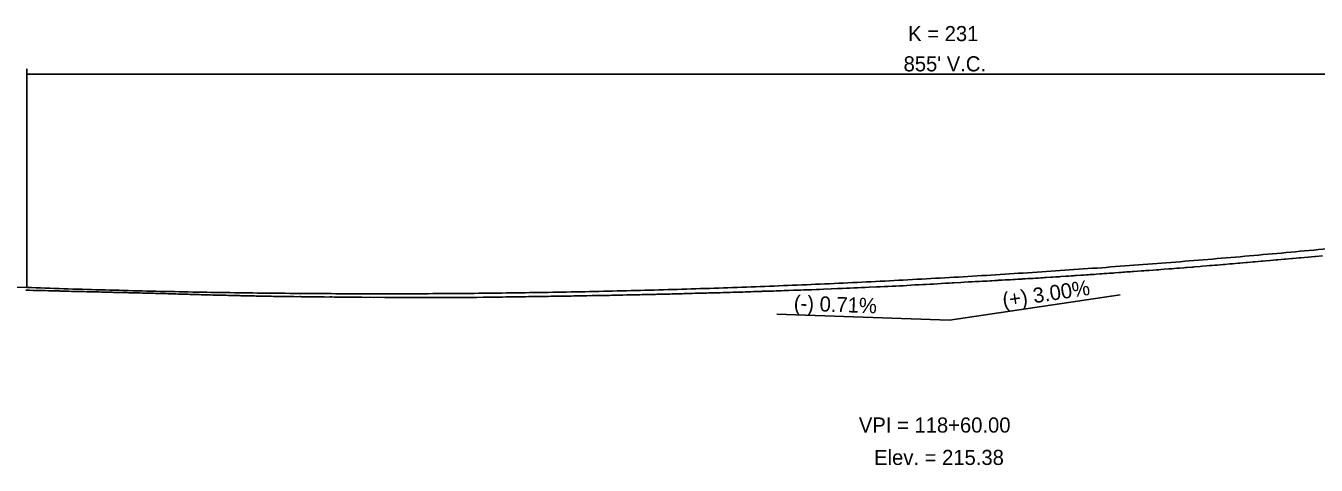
# Model space of a CAD drawing. Extents: x 1838386 to 1955906, y 719739 to 834437.
# Drawn here: x 1888795 to 1889393, y 826143 to 826346 of the extents above; entities that cross this region are included whole.
import ezdxf

# ---------------------------------------------------------------- set-up
doc = ezdxf.new("R2010")
doc.units = 0
for name, color, linetype in [('RD_DDB_GradeTX', 7, 'Continuous'), ('RD_DDB_Profile_EX', 7, 'Continuous'), ('RD_DDB_Profile_Lbl', 7, 'Continuous'), ('RD_DDB_Profile_PR', 7, 'Continuous'), ('RD_DDB_VCLbl', 7, 'Continuous')]:
    doc.layers.add(name, color=color, linetype=linetype)

msp = doc.modelspace()

# ---------------------------------------------------------------- linework, layer by layer
at = {"layer": 'RD_DDB_GradeTX'}
for p in [(1889302.2, 826221.86), (1889143.13, 826212.86)]:
    msp.add_line(p, (1889223.08, 826210.01), dxfattribs=at)
at = {"layer": 'RD_DDB_Profile_EX'}
for points in [[(1889291.05, 826231.37), (1889292.84, 826231.51), (1889293.65, 826231.56), (1889294.55, 826231.63), (1889295.3, 826231.67), (1889295.97, 826231.73), (1889297.05, 826231.8), (1889298.06, 826231.88), (1889298.87, 826231.92), (1889299.72, 826232), (1889301.56, 826232.13), (1889302.49, 826232.18), (1889303.48, 826232.28), (1889304.27, 826232.33), (1889305.08, 826232.39), (1889306.91, 826232.52), (1889307.75, 826232.58), (1889308.59, 826232.64), (1889310.37, 826232.76), (1889312.09, 826232.88), (1889313.08, 826232.93), (1889314.13, 826233.03), (1889314.85, 826233.07), (1889315.59, 826233.13), (1889317.55, 826233.27), (1889319.1, 826233.38), (1889320.07, 826233.43), (1889321.01, 826233.53), (1889322.61, 826233.64), (1889324.77, 826233.81), (1889325.44, 826233.86), (1889326.14, 826233.92), (1889327.28, 826233.98), (1889328.5, 826234.11), (1889329.63, 826234.19), (1889331.67, 826234.35), (1889332.43, 826234.4), (1889333.13, 826234.47), (1889335.45, 826234.65), (1889336.04, 826234.7), (1889336.64, 826234.75), (1889339.21, 826234.97), (1889340.15, 826235.05), (1889342.35, 826235.23), (1889343.65, 826235.33), (1889344.85, 826235.39), (1889346.12, 826235.54), (1889346.64, 826235.58), (1889347.16, 826235.62), (1889349.89, 826235.86), (1889350.66, 826235.93), (1889353.04, 826236.13), (1889354.17, 826236.22), (1889356.81, 826236.46), (1889357.24, 826236.49), (1889357.67, 826236.53), (1889359.08, 826236.61), (1889360.59, 826236.78), (1889361.19, 826236.83), (1889363.74, 826237.05), (1889364.7, 826237.13), (1889367.52, 826237.37), (1889367.86, 826237.4), (1889368.21, 826237.43), (1889369.63, 826237.51), (1889371.71, 826237.74), (1889374.45, 826237.97), (1889375.21, 826238.04), (1889378.24, 826238.32), (1889378.72, 826238.36), (1889381.7, 826238.62), (1889382.23, 826238.67), (1889383.78, 826238.76), (1889385.19, 826238.93), (1889385.74, 826238.98), (1889389.24, 826239.3), (1889392.45, 826239.59), (1889392.76, 826239.61), (1889395.94, 826239.91)], [(1889159.22, 826224.2), (1889161.29, 826224.31), (1889162.83, 826224.33), (1889164.8, 826224.44), (1889168.24, 826224.58), (1889171.22, 826224.71), (1889171.81, 826224.73), (1889173.33, 826224.76), (1889175.33, 826224.87), (1889176.93, 826224.9), (1889178.82, 826225.03), (1889180.53, 826225.06), (1889182.33, 826225.19), (1889184.05, 826225.23), (1889185.85, 826225.36), (1889189.36, 826225.52), (1889191.04, 826225.55), (1889192.86, 826225.67), (1889194.65, 826225.72), (1889196.54, 826225.84), (1889198.18, 826225.88), (1889199.93, 826226), (1889201.63, 826226.05), (1889203.37, 826226.17), (1889205.17, 826226.23), (1889207.05, 826226.37), (1889208.77, 826226.43), (1889210.77, 826226.56), (1889212.31, 826226.62), (1889214.17, 826226.75), (1889215.77, 826226.81), (1889217.59, 826226.95), (1889219.3, 826227.01), (1889221.31, 826227.16), (1889222.92, 826227.22), (1889224.42, 826227.33), (1889224.72, 826227.34), (1889225.04, 826227.37), (1889228.44, 826227.56), (1889229.91, 826227.61), (1889231.87, 826227.76), (1889233.45, 826227.81), (1889234.94, 826227.92), (1889235.26, 826227.93), (1889235.59, 826227.95), (1889237.06, 826228.01), (1889238.45, 826228.11), (1889238.86, 826228.13), (1889239.31, 826228.16), (1889240.61, 826228.21), (1889241.96, 826228.31), (1889242.34, 826228.32), (1889242.71, 826228.35), (1889244.07, 826228.4), (1889245.45, 826228.51), (1889245.8, 826228.53), (1889246.13, 826228.55), (1889247.59, 826228.6), (1889248.96, 826228.71), (1889249.4, 826228.73), (1889249.86, 826228.76), (1889251.21, 826228.81), (1889252.47, 826228.91), (1889253.59, 826228.97), (1889254.77, 826229.02), (1889255.97, 826229.11), (1889256.49, 826229.13), (1889256.99, 826229.17), (1889258.23, 826229.22), (1889259.48, 826229.32), (1889260.43, 826229.37), (1889261.75, 826229.43), (1889262.99, 826229.53), (1889263.56, 826229.55), (1889264.16, 826229.6), (1889265.37, 826229.65), (1889266.51, 826229.74), (1889267.18, 826229.77), (1889267.89, 826229.83), (1889270.01, 826229.95), (1889270.54, 826229.97), (1889271, 826230.01), (1889272.3, 826230.08), (1889273.52, 826230.18), (1889274.11, 826230.2), (1889274.73, 826230.26), (1889277.02, 826230.41), (1889277.72, 826230.44), (1889278.48, 826230.51), (1889279.49, 826230.57), (1889280.53, 826230.65), (1889281.22, 826230.69), (1889281.9, 826230.75), (1889284.03, 826230.88), (1889285.35, 826230.97), (1889286.48, 826231.03), (1889287.54, 826231.12), (1889288.29, 826231.16), (1889289.09, 826231.23), (1889290.11, 826231.29), (1889291.05, 826231.37)], [(1888795.09, 826223.99), (1888796.84, 826223.96), (1888798.5, 826223.89), (1888800.47, 826223.86), (1888802.07, 826223.79), (1888804.12, 826223.76), (1888805.65, 826223.7), (1888807.11, 826223.69), (1888807.43, 826223.67), (1888807.76, 826223.67), (1888809.22, 826223.6), (1888810.61, 826223.6), (1888811, 826223.58), (1888811.4, 826223.58), (1888812.79, 826223.52), (1888814.12, 826223.5), (1888814.58, 826223.48), (1888815.04, 826223.48), (1888816.36, 826223.42), (1888817.63, 826223.41), (1888818.15, 826223.38), (1888818.68, 826223.38), (1888819.93, 826223.33), (1888821.14, 826223.32), (1888821.72, 826223.3), (1888822.32, 826223.29), (1888823.4, 826223.24), (1888824.64, 826223.23), (1888825.02, 826223.22), (1888825.35, 826223.22), (1888826.77, 826223.16), (1888828.15, 826223.15), (1888828.55, 826223.13), (1888828.98, 826223.13), (1888830.34, 826223.08)], [(1888830.34, 826223.08), (1888831.66, 826223.05), (1888832.13, 826223.03), (1888832.61, 826223.03), (1888833.91, 826222.99), (1888835.16, 826222.98), (1888835.69, 826222.96), (1888836.25, 826222.96), (1888837.48, 826222.92), (1888838.67, 826222.9), (1888839.26, 826222.87), (1888839.88, 826222.87), (1888841.05, 826222.84), (1888842.17, 826222.83), (1888842.83, 826222.8), (1888843.51, 826222.8), (1888844.62, 826222.76), (1888845.69, 826222.75), (1888846.4, 826222.71), (1888847.14, 826222.71), (1888848.19, 826222.67), (1888849.2, 826222.65), (1888849.97, 826222.61), (1888850.77, 826222.6), (1888851.75, 826222.57), (1888852.7, 826222.55), (1888853.54, 826222.52), (1888854.4, 826222.52), (1888855.24, 826222.49), (1888856.2, 826222.46), (1888857.62, 826222.42), (1888859.73, 826222.37), (1888861.05, 826222.33), (1888862.15, 826222.28), (1888863.22, 826222.26), (1888863.93, 826222.21), (1888864.67, 826222.21), (1888865.71, 826222.17), (1888866.72, 826222.15), (1888867.5, 826222.11), (1888868.29, 826222.11), (1888869.28, 826222.07), (1888870.23, 826222.06), (1888871.06, 826222.01), (1888871.91, 826222.01), (1888872.84, 826221.97), (1888873.74, 826221.95), (1888874.62, 826221.9), (1888875.53, 826221.91), (1888876.4, 826221.88), (1888877.24, 826221.87), (1888878.18, 826221.82), (1888879.15, 826221.82), (1888879.96, 826221.8), (1888880.75, 826221.78), (1888881.75, 826221.73), (1888882.78, 826221.72), (1888883.53, 826221.7), (1888884.26, 826221.68), (1888885.31, 826221.63), (1888886.4, 826221.63), (1888887.1, 826221.61), (1888887.77, 826221.59), (1888888.88, 826221.54), (1888890.02, 826221.54), (1888890.63, 826221.52), (1888891.27, 826221.5), (1888892.36, 826221.44), (1888893.53, 826221.45), (1888894.15, 826221.44), (1888894.78, 826221.42), (1888896.66, 826221.38), (1888897.49, 826221.36), (1888898.29, 826221.35), (1888899.27, 826221.29), (1888900.28, 826221.29), (1888901.05, 826221.28), (1888901.79, 826221.26), (1888902.83, 826221.22), (1888903.9, 826221.23), (1888904.61, 826221.22), (1888905.3, 826221.2), (1888906.4, 826221.15), (1888907.52, 826221.17), (1888908.17, 826221.16), (1888908.8, 826221.14), (1888909.96, 826221.09), (1888911.15, 826221.1), (1888911.74, 826221.1), (1888912.32, 826221.09), (1888913.53, 826221.04), (1888914.78, 826221.06), (1888915.31, 826221.05), (1888915.82, 826221.04), (1888917.09, 826220.99), (1888918.41, 826221.02), (1888918.88, 826221.02), (1888919.33, 826221.01), (1888920.67, 826220.95), (1888922.05, 826220.97), (1888922.45, 826220.97)], [(1888922.45, 826220.97), (1888922.84, 826220.96), (1888924.24, 826220.9), (1888925.68, 826220.92), (1888926.01, 826220.92), (1888926.35, 826220.91), (1888927.71, 826220.87), (1888929, 826220.89), (1888929.41, 826220.89), (1888929.85, 826220.89), (1888932.33, 826220.85), (1888932.85, 826220.84), (1888933.36, 826220.84), (1888934.64, 826220.8), (1888935.97, 826220.82), (1888936.42, 826220.82), (1888936.86, 826220.81), (1888938.21, 826220.77), (1888939.61, 826220.79), (1888939.99, 826220.79), (1888940.36, 826220.78), (1888941.79, 826220.73), (1888943.25, 826220.76), (1888943.57, 826220.75), (1888943.88, 826220.75), (1888945.36, 826220.71), (1888947.39, 826220.73), (1888948.93, 826220.68), (1888950.89, 826220.7), (1888952.5, 826220.65), (1888954.39, 826220.67), (1888956.07, 826220.63), (1888957.89, 826220.66), (1888961.41, 826220.64), (1888962.92, 826220.6), (1888964.92, 826220.62), (1888966.5, 826220.58), (1888968.42, 826220.61), (1888970.07, 826220.57), (1888971.92, 826220.6), (1888973.65, 826220.55), (1888975.44, 826220.57), (1888977.23, 826220.53), (1888979.08, 826220.56), (1888980.8, 826220.52), (1888982.73, 826220.54), (1888984.58, 826220.55), (1888985.95, 826220.56), (1888987.66, 826220.52), (1888989.46, 826220.56), (1888991.24, 826220.53), (1888993.09, 826220.56), (1888994.82, 826220.54), (1888996.75, 826220.59), (1888998.4, 826220.56), (1889000.41, 826220.6), (1889001.98, 826220.59), (1889004.07, 826220.64), (1889007, 826220.68), (1889007.4, 826220.68), (1889010.8, 826220.71), (1889012.44, 826220.72), (1889014.47, 826220.76), (1889016.03, 826220.76), (1889017.51, 826220.81), (1889017.82, 826220.81), (1889018.15, 826220.82), (1889019.63, 826220.82), (1889021.03, 826220.86), (1889021.42, 826220.86), (1889021.84, 826220.87), (1889023.22, 826220.87), (1889024.53, 826220.91), (1889025.49, 826220.93), (1889026.64, 826220.94), (1889028.02, 826220.98), (1889028.6, 826220.98), (1889030.11, 826220.98), (1889031.54, 826221.02), (1889031.91, 826221.02), (1889032.29, 826221.03), (1889033.71, 826221.03), (1889035.05, 826221.07), (1889035.51, 826221.07), (1889035.99, 826221.09), (1889037.31, 826221.1), (1889038.56, 826221.13), (1889039.11, 826221.12), (1889039.68, 826221.14), (1889040.91, 826221.15), (1889042.05, 826221.18), (1889043.23, 826221.2), (1889045.58, 826221.24), (1889046.46, 826221.25), (1889047.8, 826221.26), (1889049.08, 826221.29), (1889049.6, 826221.29), (1889050.15, 826221.31), (1889051.4, 826221.32), (1889052.59, 826221.36), (1889053.2, 826221.36)], [(1889053.2, 826221.36), (1889053.86, 826221.39), (1889055.01, 826221.39), (1889056.09, 826221.43), (1889056.81, 826221.42), (1889057.56, 826221.45), (1889058.56, 826221.46), (1889059.65, 826221.49), (1889060.73, 826221.51), (1889063.1, 826221.55), (1889063.71, 826221.55), (1889064.36, 826221.57), (1889065.52, 826221.58), (1889066.61, 826221.61), (1889067.32, 826221.61), (1889068.07, 826221.64), (1889069.12, 826221.65), (1889070.12, 826221.69), (1889070.92, 826221.69), (1889071.78, 826221.72), (1889073.6, 826221.75), (1889075.11, 826221.78), (1889077.16, 826221.82), (1889078.57, 826221.86), (1889079.64, 826221.86), (1889080.64, 826221.9), (1889081.44, 826221.9), (1889082.29, 826221.94), (1889083.24, 826221.94), (1889084.14, 826221.97), (1889085.04, 826221.97), (1889085.99, 826222.02), (1889086.85, 826222.03), (1889087.65, 826222.06), (1889089.55, 826222.1), (1889091.15, 826222.14), (1889092.8, 826222.17), (1889093.76, 826222.19), (1889094.66, 826222.21), (1889095.56, 826222.21), (1889096.51, 826222.26), (1889097.36, 826222.28), (1889098.17, 826222.31), (1889099.17, 826222.3), (1889100.22, 826222.36), (1889100.97, 826222.38), (1889101.68, 826222.4), (1889102.77, 826222.4), (1889103.93, 826222.46), (1889105.19, 826222.51), (1889107.02, 826222.55), (1889107.88, 826222.57), (1889108.69, 826222.59), (1889109.68, 826222.6), (1889110.73, 826222.66), (1889111.49, 826222.68), (1889112.2, 826222.7), (1889113.29, 826222.71), (1889114.44, 826222.77), (1889115.09, 826222.78), (1889115.7, 826222.8), (1889116.89, 826222.8), (1889118.15, 826222.87), (1889119.22, 826222.91), (1889121.36, 826222.97), (1889122.72, 826223.01), (1889123.81, 826223.02), (1889124.95, 826223.08), (1889125.61, 826223.1), (1889126.23, 826223.12), (1889127.41, 826223.12), (1889128.65, 826223.19), (1889129.21, 826223.21), (1889129.74, 826223.22), (1889131.01, 826223.23), (1889132.35, 826223.32), (1889132.81, 826223.34), (1889133.25, 826223.35), (1889135.95, 826223.42), (1889136.29, 826223.44), (1889136.69, 826223.45), (1889139.14, 826223.52), (1889139.71, 826223.53), (1889140.26, 826223.55), (1889141.51, 826223.55), (1889142.85, 826223.63), (1889143.32, 826223.65), (1889143.75, 826223.66), (1889145.12, 826223.68), (1889146.55, 826223.77), (1889146.92, 826223.78), (1889147.27, 826223.79), (1889148.72, 826223.8), (1889150.78, 826223.91), (1889153.41, 826224.01), (1889154.28, 826224.04), (1889155.63, 826224.06), (1889157.03, 826224.15), (1889157.42, 826224.16), (1889157.79, 826224.18), (1889159.22, 826224.2)]]:
    msp.add_lwpolyline(points, dxfattribs=at)
at = {"layer": 'RD_DDB_Profile_PR'}
msp.add_line((1888298.08, 826242.91), (1888795.58, 826225.22), dxfattribs=at)
msp.add_spline([(1888795.58, 826225.22), (1888812.68, 826224.64), (1888829.78, 826224.13), (1888846.88, 826223.68), (1888863.98, 826223.29), (1888881.08, 826222.97), (1888898.18, 826222.71), (1888915.28, 826222.51), (1888932.38, 826222.38), (1888949.48, 826222.31), (1888966.58, 826222.31), (1888983.68, 826222.36), (1889000.78, 826222.48), (1889017.88, 826222.67), (1889034.98, 826222.92), (1889052.08, 826223.23), (1889069.18, 826223.6), (1889086.28, 826224.04), (1889103.38, 826224.54), (1889120.48, 826225.11), (1889137.58, 826225.73), (1889154.68, 826226.42), (1889171.78, 826227.18), (1889188.88, 826228), (1889205.98, 826228.88), (1889223.08, 826229.82), (1889240.18, 826230.83), (1889257.28, 826231.91), (1889274.38, 826233.04), (1889291.48, 826234.24), (1889308.58, 826235.5), (1889325.68, 826236.83), (1889342.78, 826238.22), (1889359.88, 826239.67), (1889376.98, 826241.18), (1889394.08, 826242.76), (1889411.18, 826244.4), (1889428.28, 826246.11), (1889445.38, 826247.88), (1889462.48, 826249.71), (1889479.58, 826251.61), (1889496.68, 826253.57), (1889513.78, 826255.59), (1889530.88, 826257.68), (1889547.98, 826259.83), (1889565.08, 826262.04), (1889582.18, 826264.32), (1889599.28, 826266.66), (1889616.38, 826269.06), (1889633.48, 826271.53), (1889650.58, 826274.06)], degree=3, dxfattribs=at)
at = {"layer": 'RD_DDB_VCLbl'}
for p, q in [((1888795.58, 826326.56), (1888795.58, 826225.22)), ((1888795.58, 826324.06), (1889650.58, 826324.06))]:
    msp.add_line(p, q, dxfattribs=at)

# ---------------------------------------------------------------- texts
at = {"layer": 'RD_DDB_GradeTX'}
for s, rotation, p in [('(+) 3.00%', 8.52013, (1889248.17, 826215.79)), ('(-) 0.71%', 357.96293, (1889150.88, 826214.58))]:
    msp.add_text(s, height=7, rotation=rotation, dxfattribs=at).set_placement(p)
at = {"layer": 'RD_DDB_Profile_Lbl'}
for s, p in [('VPI = 118+60.00', (1889181.12, 826158.01)), ('Elev. = 215.38', (1889188.19, 826143.01))]:
    msp.add_text(s, height=7, dxfattribs=at).set_placement(p)
at = {"layer": 'RD_DDB_VCLbl'}
for s, p in [('K = 231', (1889203.95, 826339.31)), ("855' V.C.", (1889201.83, 826325.31))]:
    msp.add_text(s, height=7, dxfattribs=at).set_placement(p)

doc.saveas('drawing.dxf')
